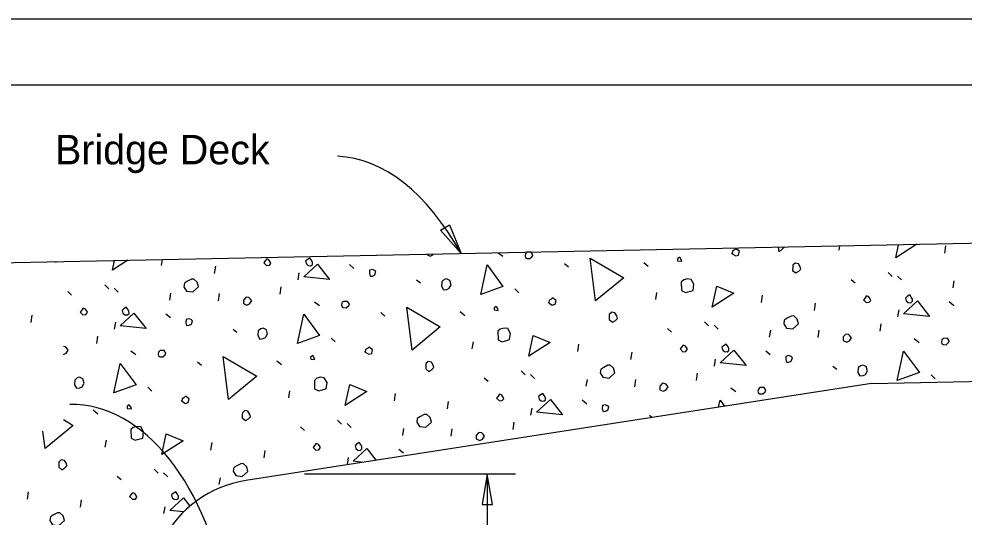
# Model space of a CAD drawing. Extents: x 0 to 30.8, y 0 to 21.2.
# Drawn here: x 3.434 to 8.286, y 17.244 to 19.8 of the extents above; entities that cross this region are included whole.
import ezdxf

# ---------------------------------------------------------------- set-up
doc = ezdxf.new("R2010")
doc.units = 0
for name, color, linetype in [('ActivePts-ConstElements', 7, 'Continuous'), ('Dimension', 7, 'Continuous'), ('Miscellaneous', 7, 'Continuous'), ('Miscellaneous1', 7, 'Continuous'), ('SupstrConc', 7, 'Continuous'), ('TextStructures', 7, 'Continuous')]:
    doc.layers.add(name, color=color, linetype=linetype)

msp = doc.modelspace()

# ---------------------------------------------------------------- linework, layer by layer
at = {"layer": 'ActivePts-ConstElements'}
msp.add_lwpolyline([(0, 0), (30.7879, 0), (30.7879, 19.4596), (0, 19.4596)], close=True, dxfattribs=at)
at = {"layer": 'Dimension'}
for p, q in [((5.9837, 17.4646), (4.9003, 17.4646)), ((5.8378, 17.4646), (5.8378, 16.9327))]:
    msp.add_line(p, q, dxfattribs=at)
for points in [[(5.7034, 18.5968), (5.5987, 18.7157), (5.6437, 18.7436)], [(5.8378, 17.4646), (5.8114, 17.3084), (5.8643, 17.3084)]]:
    msp.add_lwpolyline(points, close=True, dxfattribs=at)
for centre, major_axis, ratio, start_param, end_param in [((4.9582, 16.7281), (-0.1111, -2.3674), 0.464296, 2.502126, 3.141581), ((3.713, 16.502), (0.0174, -1.3204), 0.616683, 1.795781, 3.141615)]:
    msp.add_ellipse(centre, major_axis=major_axis, ratio=ratio, start_param=start_param, end_param=end_param, dxfattribs=at)
at = {"layer": 'Miscellaneous'}
for p, q in [((7.6445, 18.6131), (7.6484, 18.6358)), ((8.1869, 18.598), (8.1924, 18.6357)), ((5.8942, 18.6007), (5.9185, 18.5828)), ((3.6238, 18.5503), (3.6246, 18.5553)), ((4.1662, 18.5352), (4.1706, 18.5663)), ((5.1303, 18.5399), (5.1537, 18.5203)), ((6.2339, 18.5457), (6.2542, 18.5279)), ((6.6413, 18.5513), (6.6647, 18.5317)), ((4.4385, 18.4943), (4.444, 18.532)), ((4.8666, 18.4615), (4.8727, 18.4967)), ((7.8951, 18.4991), (7.916, 18.4788)), ((3.8743, 18.4363), (3.8953, 18.416)), ((5.4749, 18.4614), (5.4945, 18.4459)), ((7.7053, 18.4637), (7.7256, 18.4459)), ((7.9439, 18.4811), (7.9649, 18.4608)), ((8.2293, 18.4204), (8.2354, 18.4557)), ((3.6845, 18.4009), (3.7048, 18.3831)), ((3.9231, 18.4183), (3.9441, 18.398)), ((4.2086, 18.3576), (4.2146, 18.3929)), ((4.4579, 18.3545), (4.4633, 18.3922)), ((4.7751, 18.3877), (4.7805, 18.4254)), ((5.979, 18.4153), (5.9999, 18.395)), ((6.7027, 18.3607), (6.7088, 18.396)), ((4.951, 18.3495), (4.9768, 18.3305)), ((7.2451, 18.3456), (7.2506, 18.3833)), ((7.5175, 18.3047), (7.5229, 18.3424)), ((8.2093, 18.3503), (8.2327, 18.3307)), ((5.2921, 18.2934), (5.3124, 18.2755)), ((5.6995, 18.299), (5.7229, 18.2794)), ((7.9456, 18.2719), (7.9517, 18.3072)), ((3.4968, 18.2419), (3.5022, 18.2796)), ((3.9248, 18.2091), (3.9309, 18.2444)), ((4.1885, 18.2875), (4.2119, 18.2679)), ((6.9533, 18.2467), (6.9743, 18.2264)), ((4.5331, 18.209), (4.5527, 18.1936)), ((6.7635, 18.2114), (6.7838, 18.1935)), ((7.0021, 18.2287), (7.0231, 18.2085)), ((7.2875, 18.168), (7.2936, 18.2033)), ((7.5368, 18.165), (7.5423, 18.2026)), ((7.854, 18.1982), (7.8595, 18.2359)), ((3.8333, 18.1354), (3.8387, 18.1731)), ((5.0372, 18.1629), (5.0581, 18.1427)), ((8.0299, 18.1599), (8.0557, 18.1409)), ((4.0092, 18.0971), (4.035, 18.0781)), ((5.761, 18.1084), (5.767, 18.1437)), ((6.3034, 18.0933), (6.3088, 18.131)), ((7.2675, 18.098), (7.2909, 18.0783)), ((6.5757, 18.0524), (6.5812, 18.0901)), ((7.0038, 18.0195), (7.0099, 18.0548)), ((4.3503, 18.041), (4.3707, 18.0232)), ((4.7578, 18.0466), (4.7811, 18.027)), ((7.6121, 18.0195), (7.6317, 18.004)), ((5.8217, 17.959), (5.842, 17.9412)), ((6.0115, 17.9944), (6.0325, 17.9741)), ((6.0603, 17.9764), (6.0813, 17.9561)), ((6.3458, 17.9157), (6.3518, 17.951)), ((6.9123, 17.9458), (6.9177, 17.9835)), ((8.1162, 17.9734), (8.1371, 17.9531)), ((4.0954, 17.9106), (4.1164, 17.8903)), ((6.5951, 17.9126), (6.6005, 17.9503)), ((7.0882, 17.9076), (7.114, 17.8886)), ((4.8192, 17.856), (4.8253, 17.8913)), ((5.3616, 17.8409), (5.367, 17.8786)), ((5.634, 17.8), (5.6394, 17.8377)), ((6.3257, 17.8456), (6.3491, 17.826)), ((3.816, 17.7943), (3.8394, 17.7747)), ((6.062, 17.7672), (6.0681, 17.8025)), ((6.6703, 17.7671), (6.6849, 17.7557)), ((5.0697, 17.742), (5.0907, 17.7217)), ((5.1186, 17.724), (5.1395, 17.7038)), ((5.9705, 17.6935), (5.9759, 17.7312)), ((4.8799, 17.7067), (4.9002, 17.6888)), ((5.404, 17.6633), (5.4101, 17.6986)), ((5.6533, 17.6603), (5.6587, 17.6979)), ((3.8774, 17.6037), (3.8835, 17.639)), ((4.4198, 17.5886), (4.4252, 17.6263)), ((4.6922, 17.5477), (4.6976, 17.5854)), ((5.3839, 17.5933), (5.4073, 17.5736)), ((5.1203, 17.5148), (5.1263, 17.5501)), ((4.128, 17.4897), (4.1489, 17.4694)), ((4.1768, 17.4717), (4.1977, 17.4514)), ((3.9381, 17.4543), (3.9585, 17.4365)), ((4.4622, 17.411), (4.4683, 17.4463)), ((3.478, 17.3362), (3.4835, 17.3739)), ((3.7504, 17.2953), (3.7558, 17.333)), ((4.1785, 17.2625), (4.1846, 17.2978))]:
    msp.add_line(p, q, dxfattribs=at)
for points in [[(7.3659, 18.6302), (7.336, 18.6055)], [(8.0424, 18.6437), (7.9344, 18.5743)], [(7.9344, 18.5743), (7.949, 18.6418)], [(5.5279, 18.5934), (5.5278, 18.592), (5.5456, 18.5838), (5.5594, 18.5901), (5.5622, 18.5941)], [(6.0345, 18.5751), (6.0406, 18.5716), (6.0564, 18.5706), (6.069, 18.5817), (6.0718, 18.5903), (6.0631, 18.6035), (6.0425, 18.6031), (6.0341, 18.5957), (6.0319, 18.5848), (6.0345, 18.5751)], [(7.0954, 18.5954), (7.1138, 18.5848), (7.1283, 18.5886), (7.1334, 18.6081), (7.1144, 18.6212), (7.106, 18.6137), (7.097, 18.6087), (7.0954, 18.5954), (7.0941, 18.6002)], [(7.336, 18.6055), (7.3329, 18.6295)], [(3.9933, 18.5627), (3.9137, 18.5115)], [(3.9137, 18.5115), (3.9244, 18.5613)], [(4.6905, 18.5488), (4.7047, 18.5345), (4.7198, 18.536), (4.7275, 18.5458), (4.7262, 18.5507), (4.7175, 18.5639), (4.7059, 18.5685), (4.6982, 18.5587), (4.6905, 18.5488)], [(4.8961, 18.4771), (4.9665, 18.5426), (5.0291, 18.4636), (4.8961, 18.4771)], [(4.9095, 18.5428), (4.9193, 18.5351), (4.9327, 18.5335), (4.9411, 18.5409), (4.9409, 18.5512), (4.9353, 18.5627), (4.9272, 18.5734), (4.914, 18.5647), (4.9056, 18.5573), (4.9095, 18.5428)], [(5.8054, 18.3869), (5.8374, 18.5378), (5.9187, 18.4276), (5.8054, 18.3869)], [(6.3942, 18.3531), (6.3662, 18.5734), (6.5384, 18.472), (6.3942, 18.3531)], [(6.8152, 18.5591), (6.8365, 18.5571), (6.8339, 18.5667), (6.8258, 18.5775), (6.8151, 18.5694), (6.8152, 18.5591)], [(7.4058, 18.5284), (7.4055, 18.5102), (7.4221, 18.4966), (7.4377, 18.5059), (7.4478, 18.5164), (7.4446, 18.5285), (7.4353, 18.5441), (7.4188, 18.5474), (7.4063, 18.5363), (7.4058, 18.5284)], [(5.2329, 18.4949), (5.2368, 18.4804), (5.2495, 18.4812), (5.261, 18.4869), (5.2667, 18.504), (5.26, 18.5099), (5.2484, 18.5146), (5.2339, 18.5107), (5.2329, 18.4949)], [(4.2808, 18.4261), (4.2945, 18.4039), (4.3267, 18.3996), (4.356, 18.4256), (4.3495, 18.4497), (4.3323, 18.4658), (4.3196, 18.465), (4.2991, 18.4543), (4.2835, 18.445), (4.2808, 18.4261)], [(5.6042, 18.452), (5.6028, 18.4284), (5.6128, 18.4103), (5.6303, 18.4124), (5.6417, 18.4181), (5.6524, 18.4365), (5.6465, 18.4582), (5.6288, 18.4664), (5.6167, 18.4632), (5.6042, 18.452)], [(6.834, 18.4503), (6.8354, 18.4066), (6.8562, 18.3967), (6.8682, 18.3999), (6.8948, 18.407), (6.8991, 18.4392), (6.8848, 18.4639), (6.8659, 18.4666), (6.8466, 18.4614), (6.834, 18.4503)], [(6.9927, 18.322), (7.0157, 18.4291), (7.103, 18.393), (6.9927, 18.322)], [(4.5864, 18.3579), (4.5861, 18.3397), (4.6038, 18.3315), (4.6176, 18.3378), (4.6289, 18.3538), (4.6208, 18.3645), (4.6141, 18.3705), (4.6031, 18.3727), (4.5983, 18.3714), (4.5864, 18.3579)], [(5.0927, 18.3227), (5.0988, 18.3192), (5.1146, 18.3183), (5.1272, 18.3294), (5.1301, 18.3379), (5.1213, 18.3511), (5.1007, 18.3508), (5.0924, 18.3434), (5.0901, 18.3324), (5.0927, 18.3227)], [(6.1536, 18.343), (6.172, 18.3324), (6.1865, 18.3363), (6.1916, 18.3558), (6.1726, 18.3688), (6.1642, 18.3614), (6.1552, 18.3564), (6.1536, 18.343), (6.1523, 18.3478)], [(7.7695, 18.3593), (7.7837, 18.345), (7.7988, 18.3464), (7.8065, 18.3563), (7.8052, 18.3611), (7.7965, 18.3743), (7.7849, 18.379), (7.7772, 18.3691), (7.7695, 18.3593)], [(7.975, 18.2875), (8.0455, 18.353), (8.1081, 18.274), (7.975, 18.2875)], [(7.9885, 18.3533), (7.9983, 18.3455), (8.0117, 18.344), (8.0201, 18.3514), (8.0199, 18.3617), (8.0142, 18.3731), (8.0062, 18.3839), (7.993, 18.3752), (7.9846, 18.3678), (7.9885, 18.3533)], [(3.7487, 18.2965), (3.7629, 18.2822), (3.778, 18.2837), (3.7858, 18.2935), (3.7845, 18.2983), (3.7758, 18.3115), (3.7642, 18.3162), (3.7564, 18.3063), (3.7487, 18.2965)], [(3.9543, 18.2248), (4.0247, 18.2902), (4.0873, 18.2112), (3.9543, 18.2248)], [(3.9677, 18.2905), (3.9776, 18.2828), (3.9909, 18.2812), (3.9993, 18.2886), (3.9991, 18.2989), (3.9935, 18.3103), (3.9854, 18.3211), (3.9722, 18.3124), (3.9639, 18.305), (3.9677, 18.2905)], [(5.4524, 18.1008), (5.4245, 18.321), (5.5966, 18.2196), (5.4524, 18.1008)], [(5.8735, 18.3068), (5.8947, 18.3047), (5.8921, 18.3144), (5.8841, 18.3251), (5.8733, 18.3171), (5.8735, 18.3068)], [(6.464, 18.2761), (6.4637, 18.2579), (6.4803, 18.2442), (6.4959, 18.2536), (6.5061, 18.264), (6.5028, 18.2761), (6.4935, 18.2917), (6.477, 18.2951), (6.4645, 18.284), (6.464, 18.2761)], [(4.2912, 18.2426), (4.295, 18.2281), (4.3078, 18.2289), (4.3192, 18.2345), (4.325, 18.2516), (4.3182, 18.2576), (4.3066, 18.2622), (4.2921, 18.2583), (4.2912, 18.2426)], [(4.8636, 18.1345), (4.8957, 18.2855), (4.9769, 18.1753), (4.8636, 18.1345)], [(7.3598, 18.2366), (7.3735, 18.2144), (7.4057, 18.21), (7.435, 18.236), (7.4285, 18.2602), (7.4113, 18.2762), (7.3985, 18.2754), (7.3781, 18.2648), (7.3625, 18.2554), (7.3598, 18.2366)], [(4.6624, 18.1997), (4.661, 18.176), (4.671, 18.158), (4.6885, 18.1601), (4.7, 18.1657), (4.7106, 18.1841), (4.7048, 18.2059), (4.687, 18.214), (4.675, 18.2108), (4.6624, 18.1997)], [(5.8923, 18.1979), (5.8936, 18.1543), (5.9144, 18.1443), (5.9265, 18.1476), (5.953, 18.1547), (5.9573, 18.1869), (5.943, 18.2115), (5.9241, 18.2142), (5.9048, 18.2091), (5.8923, 18.1979)], [(6.0509, 18.0696), (6.0739, 18.1767), (6.1613, 18.1406), (6.0509, 18.0696)], [(7.6653, 18.1683), (7.665, 18.1501), (7.6828, 18.1419), (7.6966, 18.1482), (7.7079, 18.1642), (7.6998, 18.175), (7.693, 18.1809), (7.6821, 18.1832), (7.6772, 18.1819), (7.6653, 18.1683)], [(8.1717, 18.1332), (8.1778, 18.1296), (8.1936, 18.1287), (8.2061, 18.1398), (8.209, 18.1484), (8.2003, 18.1616), (8.1797, 18.1612), (8.1713, 18.1538), (8.1691, 18.1428), (8.1717, 18.1332)], [(3.6624, 18.0793), (3.6759, 18.0854), (3.6871, 18.1014), (3.679, 18.1122), (3.6723, 18.1181), (3.6624, 18.1202)], [(4.1509, 18.0704), (4.1571, 18.0669), (4.1728, 18.0659), (4.1854, 18.077), (4.1883, 18.0856), (4.1796, 18.0988), (4.159, 18.0984), (4.1506, 18.091), (4.1484, 18.0801), (4.1509, 18.0704)], [(5.2118, 18.0907), (5.2302, 18.0801), (5.2447, 18.0839), (5.2498, 18.1034), (5.2308, 18.1165), (5.2225, 18.109), (5.2134, 18.104), (5.2118, 18.0907), (5.2105, 18.0955)], [(6.8277, 18.1069), (6.8419, 18.0926), (6.857, 18.0941), (6.8647, 18.1039), (6.8634, 18.1088), (6.8547, 18.1219), (6.8431, 18.1266), (6.8354, 18.1168), (6.8277, 18.1069)], [(7.0333, 18.0352), (7.1037, 18.1007), (7.1663, 18.0217), (7.0333, 18.0352)], [(7.0467, 18.1009), (7.0565, 18.0932), (7.0699, 18.0916), (7.0783, 18.099), (7.0781, 18.1093), (7.0725, 18.1208), (7.0644, 18.1315), (7.0512, 18.1228), (7.0428, 18.1154), (7.0467, 18.1009)], [(4.5106, 17.8484), (4.4827, 18.0687), (4.6548, 17.9673), (4.5106, 17.8484)], [(4.9317, 18.0544), (4.9529, 18.0524), (4.9504, 18.062), (4.9423, 18.0728), (4.9315, 18.0647), (4.9317, 18.0544)], [(7.3701, 18.053), (7.374, 18.0385), (7.3867, 18.0393), (7.3982, 18.045), (7.4039, 18.0621), (7.3972, 18.068), (7.3856, 18.0727), (7.3711, 18.0688), (7.3701, 18.053)], [(7.9426, 17.945), (7.9746, 18.0959), (8.0559, 17.9857), (7.9426, 17.945)], [(3.9218, 17.8822), (3.9539, 18.0331), (4.0352, 17.9229), (3.9218, 17.8822)], [(5.5222, 18.0237), (5.5219, 18.0055), (5.5385, 17.9919), (5.5542, 18.0012), (5.5643, 18.0117), (5.5611, 18.0238), (5.5517, 18.0394), (5.5353, 18.0427), (5.5227, 18.0316), (5.5222, 18.0237)], [(6.418, 17.9842), (6.4317, 17.962), (6.4639, 17.9577), (6.4932, 17.9837), (6.4867, 18.0078), (6.4695, 18.0239), (6.4568, 18.0231), (6.4363, 18.0124), (6.4207, 18.0031), (6.418, 17.9842)], [(7.7414, 18.0101), (7.74, 17.9864), (7.75, 17.9684), (7.7675, 17.9705), (7.7789, 17.9762), (7.7896, 17.9946), (7.7837, 18.0163), (7.766, 18.0245), (7.7539, 18.0212), (7.7414, 18.0101)], [(3.7206, 17.9473), (3.7192, 17.9237), (3.7292, 17.9056), (3.7468, 17.9077), (3.7582, 17.9134), (3.7688, 17.9318), (3.763, 17.9535), (3.7453, 17.9617), (3.7332, 17.9585), (3.7206, 17.9473)], [(4.9505, 17.9456), (4.9518, 17.9019), (4.9726, 17.892), (4.9847, 17.8952), (5.0113, 17.9023), (5.0156, 17.9345), (5.0012, 17.9592), (4.9824, 17.9619), (4.963, 17.9567), (4.9505, 17.9456)], [(5.1091, 17.8173), (5.1322, 17.9244), (5.2195, 17.8883), (5.1091, 17.8173)], [(6.7236, 17.916), (6.7233, 17.8978), (6.741, 17.8896), (6.7548, 17.8959), (6.7661, 17.9118), (6.758, 17.9226), (6.7513, 17.9286), (6.7403, 17.9308), (6.7355, 17.9295), (6.7236, 17.916)], [(7.2299, 17.8808), (7.236, 17.8773), (7.2518, 17.8764), (7.2644, 17.8875), (7.2673, 17.896), (7.2585, 17.9092), (7.2379, 17.9089), (7.2296, 17.9014), (7.2273, 17.8905), (7.2299, 17.8808)], [(4.2701, 17.8383), (4.2884, 17.8277), (4.3029, 17.8316), (4.3081, 17.8511), (4.289, 17.8641), (4.2807, 17.8567), (4.2717, 17.8517), (4.2701, 17.8383), (4.2688, 17.8432)], [(5.8859, 17.8546), (5.9001, 17.8403), (5.9152, 17.8417), (5.923, 17.8516), (5.9217, 17.8564), (5.913, 17.8696), (5.9014, 17.8743), (5.8936, 17.8644), (5.8859, 17.8546)], [(6.1049, 17.8486), (6.1148, 17.8409), (6.1281, 17.8393), (6.1365, 17.8467), (6.1363, 17.857), (6.1307, 17.8684), (6.1226, 17.8792), (6.1094, 17.8705), (6.1011, 17.8631), (6.1049, 17.8486)], [(3.9899, 17.8021), (4.0112, 17.8), (4.0086, 17.8097), (4.0005, 17.8204), (3.9897, 17.8124), (3.9899, 17.8021)], [(6.0915, 17.7828), (6.1619, 17.8483), (6.2245, 17.7693), (6.0915, 17.7828)], [(6.4284, 17.8006), (6.4322, 17.7862), (6.445, 17.787), (6.4564, 17.7926), (6.4622, 17.8097), (6.4554, 17.8157), (6.4438, 17.8203), (6.4293, 17.8164), (6.4284, 17.8006)], [(7.0254, 17.8086), (7.0328, 17.8436), (7.0552, 17.8132)], [(4.5805, 17.7714), (4.5802, 17.7532), (4.5968, 17.7395), (4.6124, 17.7489), (4.6225, 17.7594), (4.6193, 17.7714), (4.6099, 17.787), (4.5935, 17.7904), (4.5809, 17.7793), (4.5805, 17.7714)], [(5.4762, 17.7319), (5.4899, 17.7097), (5.5221, 17.7054), (5.5514, 17.7313), (5.545, 17.7555), (5.5277, 17.7715), (5.515, 17.7707), (5.4945, 17.7601), (5.4789, 17.7507), (5.4762, 17.7319)], [(3.6624, 17.7448), (3.713, 17.7149), (3.5689, 17.5961)], [(4.0087, 17.6932), (4.0101, 17.6496), (4.0308, 17.6396), (4.0429, 17.6429), (4.0695, 17.65), (4.0738, 17.6822), (4.0594, 17.7068), (4.0406, 17.7095), (4.0213, 17.7044), (4.0087, 17.6932)], [(3.5689, 17.5961), (3.5577, 17.6845)], [(4.1673, 17.5649), (4.1904, 17.672), (4.2777, 17.6359), (4.1673, 17.5649)], [(5.7818, 17.6636), (5.7815, 17.6454), (5.7992, 17.6372), (5.8131, 17.6435), (5.8243, 17.6595), (5.8162, 17.6703), (5.8095, 17.6762), (5.7985, 17.6785), (5.7937, 17.6772), (5.7818, 17.6636)], [(4.9441, 17.6022), (4.9583, 17.5879), (4.9735, 17.5894), (4.9812, 17.5992), (4.9799, 17.6041), (4.9712, 17.6172), (4.9596, 17.6219), (4.9519, 17.6121), (4.9441, 17.6022)], [(5.1632, 17.5962), (5.173, 17.5885), (5.1864, 17.5869), (5.1947, 17.5943), (5.1946, 17.6046), (5.1889, 17.6161), (5.1808, 17.6268), (5.1676, 17.6181), (5.1593, 17.6107), (5.1632, 17.5962)], [(5.1497, 17.5305), (5.2202, 17.596), (5.2681, 17.5355)], [(3.6387, 17.519), (3.6384, 17.5008), (3.655, 17.4872), (3.6706, 17.4965), (3.6807, 17.507), (3.6775, 17.5191), (3.6681, 17.5347), (3.6517, 17.538), (3.6392, 17.5269), (3.6387, 17.519)], [(4.5344, 17.4795), (4.5482, 17.4573), (4.5804, 17.453), (4.6096, 17.479), (4.6032, 17.5031), (4.5859, 17.5192), (4.5732, 17.5184), (4.5528, 17.5077), (4.5372, 17.4984), (4.5344, 17.4795)], [(5.2018, 17.5252), (5.1497, 17.5305)], [(4.0024, 17.3499), (4.0165, 17.3356), (4.0317, 17.337), (4.0394, 17.3469), (4.0381, 17.3517), (4.0294, 17.3649), (4.0178, 17.3696), (4.0101, 17.3597), (4.0024, 17.3499)], [(4.2214, 17.3439), (4.2312, 17.3362), (4.2446, 17.3346), (4.2529, 17.342), (4.2528, 17.3523), (4.2471, 17.3637), (4.2391, 17.3745), (4.2259, 17.3658), (4.2175, 17.3584), (4.2214, 17.3439)], [(4.2079, 17.2782), (4.2784, 17.3436), (4.3122, 17.301)], [(4.2791, 17.2709), (4.2079, 17.2782)], [(3.5927, 17.2272), (3.6064, 17.205), (3.6386, 17.2007), (3.6679, 17.2266), (3.6614, 17.2508), (3.6441, 17.2668), (3.6314, 17.266), (3.611, 17.2554), (3.5954, 17.246), (3.5927, 17.2272)]]:
    msp.add_lwpolyline(points, dxfattribs=at)
at = {"layer": 'Miscellaneous1'}
msp.add_lwpolyline([(0, 19.8), (30.8, 19.8), (30.8, 0), (0, 0)], close=True, dxfattribs=at)
at = {"layer": 'SupstrConc'}
for p, q in [((0.6169, 18.4952), (10.8054, 18.699)), ((7.811, 17.9306), (10.8054, 17.9905)), ((7.811, 17.9306), (4.5987, 17.4315))]:
    msp.add_line(p, q, dxfattribs=at)
msp.add_arc((4.6882, 16.8551), 0.5833, 98.8325, 206.4422, dxfattribs=at)

# ---------------------------------------------------------------- texts
at = {"layer": 'TextStructures'}
msp.add_text('Bridge Deck', height=0.1512, dxfattribs=at).set_placement((3.6196, 19.054))

doc.saveas('drawing.dxf')
